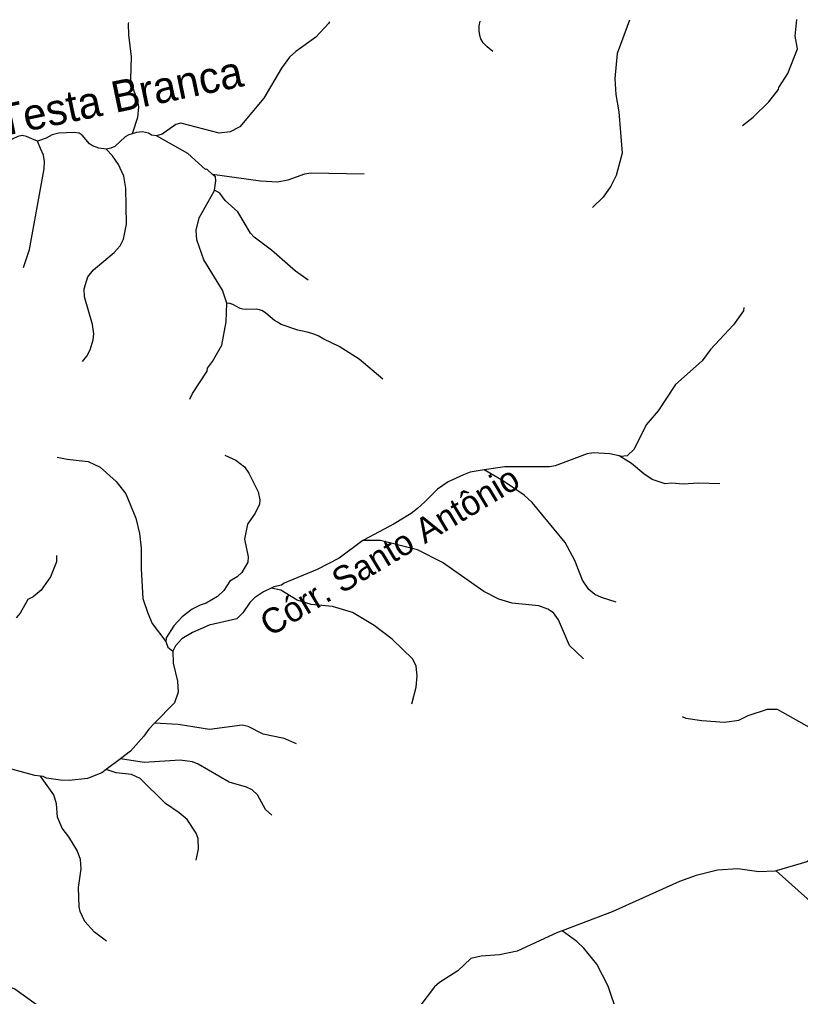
# Model space of a CAD drawing. Extents: x 280.4 to 335.6, y 8893.9 to 8949.5.
# Drawn here: x 319.18 to 324.16, y 8943.22 to 8949.46 of the extents above; entities that cross this region are included whole.
import ezdxf
from ezdxf.enums import TextEntityAlignment as Align

# ---------------------------------------------------------------- set-up
doc = ezdxf.new("R2010")
doc.units = 0
doc.header["$LTSCALE"] = 0.064
doc.linetypes.add('LONG_DASHED', pattern=[7.5, 6, -1.5])
doc.layers.add('61', color=7, linetype='Continuous')
doc.layers.add('7', color=7, linetype='Continuous', lineweight=25)
doc.layers.add('9', color=7, linetype='LONG_DASHED', lineweight=25)

msp = doc.modelspace()

# ---------------------------------------------------------------- linework, layer by layer
at = {"layer": '7'}
msp.add_line((319.8226, 8944.7367), (319.73, 8944.6669), dxfattribs=at)
for points in [[(319.8721, 8949.439), (319.87, 8949.4314), (319.872, 8949.3612), (319.8896, 8949.2196), (319.885, 8949.0782), (319.8916, 8949.043), (319.931, 8948.9388), (319.9376, 8948.9022), (319.9312, 8948.8327), (319.8954, 8948.7296)], [(321.156, 8949.4451), (321.1503, 8949.4344), (321.0689, 8949.3465), (320.9409, 8949.2553), (320.9015, 8949.2183), (320.8499, 8949.1478), (320.7368, 8948.9567), (320.5849, 8948.7744), (320.5213, 8948.7411), (320.4517, 8948.7335), (320.2063, 8948.7972), (320.1749, 8948.788), (320.0884, 8948.7275), (320.0523, 8948.7157)], [(322.1991, 8949.2547), (322.1632, 8949.2839), (322.1385, 8949.3097), (322.124, 8949.3355), (322.1161, 8949.3568), (322.1116, 8949.387), (322.1128, 8949.4195), (322.1195, 8949.4495)], [(319.7304, 8948.63), (319.6842, 8948.6361), (319.6432, 8948.6516), (319.6232, 8948.6644), (319.5774, 8948.7194), (319.5585, 8948.732), (319.5258, 8948.7365), (319.4283, 8948.7332), (319.3859, 8948.7221), (319.3461, 8948.7012), (319.2909, 8948.6828)], [(320.0523, 8948.7157), (320.0194, 8948.7208), (320.0014, 8948.7324), (319.9615, 8948.7408), (319.9247, 8948.7379), (319.8954, 8948.7296)], [(319.2909, 8948.6828), (319.2552, 8948.6974), (319.2216, 8948.7125), (319.1933, 8948.7181), (319.165, 8948.7125), (319.1299, 8948.694), (319.0638, 8948.6484), (319.0075, 8948.625), (318.9493, 8948.6216), (318.8645, 8948.6373), (318.8335, 8948.6373), (318.7767, 8948.6199), (318.7163, 8948.5883), (318.6691, 8948.5691)], [(319.2031, 8947.8752), (319.2404, 8947.9889), (319.3349, 8948.5056), (319.3362, 8948.5526), (319.3296, 8948.5934), (319.3107, 8948.6343), (319.2909, 8948.6828)], [(319.8954, 8948.7296), (319.8752, 8948.7224), (319.8509, 8948.7088), (319.7862, 8948.6485), (319.7592, 8948.6361), (319.7304, 8948.63)], [(320.4103, 8948.4696), (320.3727, 8948.503), (320.3648, 8948.5012), (320.2511, 8948.6039), (320.0523, 8948.7157)], [(319.5782, 8947.2742), (319.6068, 8947.308), (319.6287, 8947.348), (319.6481, 8947.4125), (319.6512, 8947.4502), (319.6427, 8947.511), (319.5922, 8947.6883), (319.5907, 8947.7387), (319.6132, 8947.8155), (319.6493, 8947.8597), (319.7804, 8947.9702), (319.8204, 8948.0133), (319.8415, 8948.0563), (319.8591, 8948.1521), (319.856, 8948.3809), (319.8435, 8948.4577), (319.8085, 8948.5329), (319.7697, 8948.5879), (319.7304, 8948.63)], [(321.3781, 8948.4706), (321.0396, 8948.4764), (320.9979, 8948.4707), (320.8911, 8948.4336), (320.8236, 8948.4201), (320.7164, 8948.4266), (320.4103, 8948.4696)], [(320.4211, 8948.3694), (320.4312, 8948.4278), (320.4283, 8948.4536), (320.4103, 8948.4696)], [(320.5006, 8947.6467), (320.4728, 8947.73), (320.3536, 8947.9238), (320.3085, 8948.0518), (320.3055, 8948.1129), (320.325, 8948.1929), (320.4198, 8948.3616), (320.4211, 8948.3694)], [(321.0212, 8947.7937), (320.9395, 8947.8519), (320.7868, 8947.985), (320.675, 8948.0682), (320.6522, 8948.0943), (320.5712, 8948.2313), (320.4911, 8948.3033), (320.4563, 8948.3489), (320.4211, 8948.3694)], [(320.2636, 8947.0334), (320.281, 8947.0692), (320.3751, 8947.2129), (320.3776, 8947.2315), (320.4098, 8947.274), (320.4683, 8947.3792), (320.4958, 8947.5284), (320.5006, 8947.6467)], [(321.4972, 8947.162), (321.3456, 8947.2889), (321.219, 8947.3698), (321.1196, 8947.4165), (321.0836, 8947.4375), (321.0559, 8947.4496), (321.0366, 8947.4556), (321.0137, 8947.4616), (320.9548, 8947.4749), (320.8484, 8947.5111), (320.8237, 8947.5245), (320.8061, 8947.5364), (320.7509, 8947.5839), (320.7289, 8947.598), (320.7092, 8947.6039), (320.6879, 8947.6076), (320.6251, 8947.6064), (320.603, 8947.6093), (320.5853, 8947.6136), (320.5389, 8947.6378), (320.5202, 8947.6438), (320.5006, 8947.6467)], [(323.8037, 8947.6201), (323.8, 8947.5989), (323.7379, 8947.509), (323.5892, 8947.3505), (323.537, 8947.2777), (323.3675, 8947.1268), (323.2565, 8946.9589), (323.1785, 8946.87), (323.102, 8946.7131), (323.0582, 8946.671), (323.0175, 8946.6682), (323.0074, 8946.6706)], [(320.488, 8946.6765), (320.5586, 8946.6428), (320.613, 8946.6011), (320.6418, 8946.5608), (320.7019, 8946.4411), (320.7116, 8946.3896), (320.7099, 8946.3619), (320.6813, 8946.3058), (320.6326, 8946.2352), (320.6128, 8946.1397), (320.6379, 8946.0257), (320.6349, 8945.9915), (320.5961, 8945.9262), (320.5665, 8945.8993), (320.521, 8945.8718), (320.482, 8945.8121), (320.4419, 8945.7721), (320.3698, 8945.731), (320.3303, 8945.7184), (320.2801, 8945.6922), (320.216, 8945.6437), (320.1632, 8945.5861), (320.113, 8945.5097), (320.1109, 8945.4851)], [(323.0074, 8946.6706), (322.9467, 8946.6849), (322.8419, 8946.6896), (322.8018, 8946.6833), (322.5972, 8946.6086), (322.5621, 8946.6019), (322.2772, 8946.6015), (322.1437, 8946.5815)], [(319.4172, 8946.6628), (319.4817, 8946.6495), (319.6146, 8946.6352), (319.6925, 8946.5992), (319.7931, 8946.5078), (319.855, 8946.4295), (319.9199, 8946.2738), (319.9427, 8946.1762), (319.9536, 8946.0819), (319.9538, 8945.9493), (319.9653, 8945.7604), (319.9955, 8945.6653), (320.0233, 8945.6005), (320.1109, 8945.4851)], [(323.6492, 8946.493), (323.5121, 8946.4962), (323.4161, 8946.4897), (323.3414, 8946.4975), (323.3, 8946.4931), (323.2178, 8946.521), (323.1644, 8946.5561), (323.085, 8946.6224), (323.0074, 8946.6706)], [(322.1437, 8946.5815), (322.0558, 8946.5669), (322.0122, 8946.5505), (321.9143, 8946.5057), (321.8462, 8946.4582), (321.7646, 8946.3786), (321.7177, 8946.3353), (321.6774, 8946.303), (321.5696, 8946.2374), (321.3742, 8946.1334), (321.3693, 8946.1298)], [(322.9866, 8945.7369), (322.8944, 8945.7659), (322.8522, 8945.7857), (322.8128, 8945.817), (322.772, 8945.8763), (322.7232, 8946.0025), (322.6627, 8946.117), (322.4503, 8946.3727), (322.4005, 8946.4193), (322.2689, 8946.5097), (322.1437, 8946.5815)], [(321.3693, 8946.1298), (321.2182, 8946.0187), (321.0779, 8945.9451), (320.8669, 8945.8586), (320.8499, 8945.8452), (320.8018, 8945.8349), (320.7837, 8945.8263)], [(322.7796, 8945.3738), (322.6895, 8945.4603), (322.6196, 8945.6245), (322.5865, 8945.6688), (322.5519, 8945.6926), (322.4932, 8945.7123), (322.3239, 8945.731), (322.2377, 8945.7551), (322.1429, 8945.8043), (321.878, 8945.9904), (321.7192, 8946.0707), (321.4827, 8946.1304), (321.3693, 8946.1298)], [(319.4135, 8946.0347), (319.4128, 8945.9952), (319.3756, 8945.8984), (319.3143, 8945.8139), (319.2632, 8945.7705), (319.2302, 8945.7544), (319.1811, 8945.6661), (319.1548, 8945.6366)], [(320.7837, 8945.8263), (320.735, 8945.8032), (320.6766, 8945.7636), (320.6483, 8945.7354), (320.6028, 8945.6693), (320.5643, 8945.6296), (320.387, 8945.5903), (320.2816, 8945.5437), (320.2128, 8945.5013), (320.172, 8945.4577), (320.1556, 8945.4231)], [(321.6824, 8945.0863), (321.7097, 8945.1942), (321.7161, 8945.2652), (321.711, 8945.3277), (321.6878, 8945.373), (321.5561, 8945.4997), (321.4425, 8945.5877), (321.3034, 8945.6708), (321.1747, 8945.7087), (321.0386, 8945.722), (320.9494, 8945.7497), (320.8459, 8945.8131), (320.7837, 8945.8263)], [(320.1109, 8945.4851), (320.1236, 8945.4494), (320.1556, 8945.4231)], [(320.1556, 8945.4231), (320.1554, 8945.4227), (320.1577, 8945.3466), (320.1853, 8945.2317), (320.1902, 8945.1615), (320.1674, 8945.093), (320.0399, 8944.9626)], [(323.409, 8945.007), (323.4335, 8944.9965), (323.5348, 8944.9798), (323.6799, 8944.9689), (323.7719, 8944.9831), (323.8298, 8945.0129), (323.9543, 8945.0533), (324.016, 8945.0524), (324.2198, 8944.9388), (324.3362, 8944.8948), (324.3709, 8944.8738), (324.3877, 8944.8425), (324.3993, 8944.8039)], [(320.0399, 8944.9626), (320.0027, 8944.9246), (319.9717, 8944.8799), (319.8858, 8944.7843), (319.8226, 8944.7367)], [(320.9465, 8944.8325), (320.8678, 8944.8666), (320.7334, 8944.8923), (320.6381, 8944.9415), (320.5997, 8944.951), (320.3902, 8944.9241), (320.191, 8944.9559), (320.0399, 8944.9626)], [(319.3117, 8944.6247), (319.2739, 8944.6302), (319.1341, 8944.6668), (318.933, 8944.7457), (318.8661, 8944.7513), (318.7739, 8944.7407), (318.7515, 8944.7342)], [(320.7886, 8944.3756), (320.7473, 8944.411), (320.6957, 8944.505), (320.6636, 8944.537), (320.6266, 8944.5541), (320.515, 8944.5866), (320.3182, 8944.7017), (320.2806, 8944.7174), (320.2024, 8944.7273), (319.9721, 8944.7114), (319.8226, 8944.7367)], [(319.73, 8944.6669), (319.7015, 8944.6454), (319.6114, 8944.609), (319.4946, 8944.5978), (319.4386, 8944.5994), (319.3492, 8944.6128), (319.3285, 8944.6223), (319.3117, 8944.6247)], [(319.7318, 8943.5712), (319.6562, 8943.6288), (319.5932, 8943.6971), (319.5651, 8943.7597), (319.5587, 8943.7911), (319.5538, 8943.9131), (319.5713, 8944.0333), (319.5664, 8944.0932), (319.5442, 8944.1499), (319.4914, 8944.2363), (319.4483, 8944.2924), (319.4192, 8944.3626), (319.4129, 8944.4481), (319.3967, 8944.5057), (319.3117, 8944.6247)], [(320.3049, 8944.0875), (320.3191, 8944.1598), (320.3167, 8944.2261), (320.3047, 8944.26), (320.2485, 8944.3478), (320.1967, 8944.3914), (320.1097, 8944.4498), (319.9465, 8944.6108), (319.8921, 8944.636), (319.7946, 8944.6457), (319.73, 8944.6669)], [(319.4625, 8943.0629), (319.3518, 8943.1173), (319.1473, 8943.2634), (319.1022, 8943.2832), (318.9404, 8943.3071), (318.7025, 8943.4163), (318.5373, 8943.5115), (318.373, 8943.6324), (318.2894, 8943.7208), (318.231, 8943.8085), (318.1513, 8943.983), (318.0958, 8944.0646), (318.0478, 8944.1159), (317.9296, 8944.1715), (317.8394, 8944.2139), (317.7235, 8944.2382), (317.638, 8944.2668), (317.5637, 8944.3067), (317.4833, 8944.3597), (317.3938, 8944.4325), (317.339, 8944.4902), (317.2758, 8944.5371), (317.1869, 8944.5672), (317.1169, 8944.5733)], [(324.3938, 8944.2374), (324.2738, 8944.1234), (324.2047, 8944.0768), (324.0094, 8944.0191)], [(324.0094, 8944.0191), (324.0025, 8944.0171), (323.8991, 8944.0131), (323.7638, 8944.0331), (323.6352, 8944.0236), (323.4993, 8943.9905), (323.3913, 8943.9513), (322.9623, 8943.7582), (322.6434, 8943.6376)], [(324.6727, 8943.2345), (324.4598, 8943.3877), (324.4337, 8943.4174), (324.3897, 8943.4886), (324.293, 8943.7454), (324.28, 8943.7598), (324.2788, 8943.7701), (324.251, 8943.8042), (324.0094, 8944.0191)], [(322.6434, 8943.6376), (322.6119, 8943.6257), (322.3545, 8943.5073), (322.2424, 8943.4828), (322.1242, 8943.4758), (322.0597, 8943.4596), (321.9757, 8943.3812), (321.86, 8943.3071), (321.8269, 8943.2788), (321.7395, 8943.1632), (321.6899, 8943.0842), (321.6293, 8943.0127), (321.4863, 8942.8786), (321.4133, 8942.8255)], [(323.8022, 8941.9733), (323.8031, 8941.989), (323.7758, 8942.0709), (323.7336, 8942.1648), (323.6086, 8942.3833), (323.5647, 8942.5098), (323.5519, 8942.6364), (323.5385, 8942.7064), (323.4744, 8942.7782), (323.3888, 8942.837), (323.3192, 8942.8762), (323.2872, 8942.8942), (323.1369, 8942.9566), (323.0483, 8943.029), (322.9955, 8943.1073), (322.9365, 8943.2824), (322.8647, 8943.4233), (322.7805, 8943.5268), (322.7373, 8943.5683), (322.6434, 8943.6376)]]:
    msp.add_lwpolyline(points, dxfattribs=at)
at = {"layer": '9'}
for points in [[(323.0728, 8949.454), (323.0578, 8949.4143), (322.9929, 8949.2425), (322.9795, 8949.0822), (322.9855, 8948.9795), (323.0052, 8948.8693), (323.0255, 8948.6047), (322.9882, 8948.4616), (322.9534, 8948.3935), (322.9047, 8948.3246), (322.8372, 8948.2585)], [(323.7948, 8948.781), (323.8628, 8948.8343), (323.9624, 8948.9328), (324.0249, 8949.0122), (324.0257, 8949.0242), (324.0833, 8949.1133), (324.1449, 8949.2718), (324.131, 8949.3524), (324.1414, 8949.4589)]]:
    msp.add_lwpolyline(points, dxfattribs=at)

# ---------------------------------------------------------------- texts
at = {"layer": '61'}
for s, height, rotation, p in [('Ribeirão Testa Branca', 0.2, 11.768, (319.3143, 8948.7633)), ('Córr. Santo Antônio', 0.16, 30.964, (321.5815, 8945.996))]:
    msp.add_text(s, height=height, rotation=rotation, dxfattribs=at).set_placement(p, align=Align.CENTER)

doc.saveas('drawing.dxf')
